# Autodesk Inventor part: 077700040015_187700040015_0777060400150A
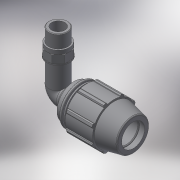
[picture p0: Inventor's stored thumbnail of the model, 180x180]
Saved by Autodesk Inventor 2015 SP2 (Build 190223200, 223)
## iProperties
Created: 2017-02
Part Number: 077700040015_187700040015_0777060400150A
Material: Generic
Description: PLASSON 90° ELBOW MALE WITH INTEGRAL BRASS THREAD 40-1.1/2"
Document SubType Name: Modeling
Designer: KIM
Mass: 174.249 g
Surface Area: 431.906 cm^2
Volume: 174.249 cm^3
Density: 1 g/cm^3
Appearance: Default
Author: KIM
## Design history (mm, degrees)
derived "07770.ipt"
feature "Solid1::07770.ipt"
tag "TaggingFeature1"
body "Solid1"
other parameters: "d4" = 10.33333, "d5" = 31, "d7" = 82, "d9" = 17.71429, "d11" = 4.13333, "d13" = 120 deg, "d14" = 56, "d15" = 12 deg, "d16" = 71.34, "d18" = 2, "d19" = 35 deg, "d20" = 17.5 deg, "d21" = 76.26, "d23" = 0, "d25" = 360 deg, "d27" = 1.64, "d33" = 0.8, "d42" = 45.88, "d43" = 2.46, "d46" = 1.2, "d51" = 124, "d68" = 8.26667, "d72" = 89, "d73" = 47.803, "d74" = 22, "d75" = 54.97345, "d76" = 33.4621, "d79" = 19.1212, "d80" = 1.43409, "d83" = 0, "d84" = 0, "d91" = 61.5, "d93" = 84, "d94" = 47.803, "d95" = 33.4621, "d96" = 8.26667, "d97" = 50 deg, "d98" = 2.06667, "d99" = 69.1998, "d100" = 2.06667, "d101" = 2.06667, "d105" = 2.2, "d106" = 57.3636, "d107" = 22, "d108" = 13.2, "d109" = 0, "E_" = 82, "A_" = 124, "l_" = 84, "l_2" = 22, "A_1" = 89, "R_" = 47.803
